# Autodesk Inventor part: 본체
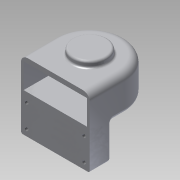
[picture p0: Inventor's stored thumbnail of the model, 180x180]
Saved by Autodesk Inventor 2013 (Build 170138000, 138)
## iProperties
Created: 2015-02
Part Number: 본체
Material: 알루미늄 6061
Document SubType Name: Modeling
Designer: Administrator
Density: 2.71 g/cm^3
Mass: 737.912 g
Surface Area: 727.955 cm^2
Volume: 272.292 cm^3
Author: Administrator
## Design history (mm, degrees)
sketch "스케치1"
  geometry: L1 (-50, -50)-(50, -50); L2 (50, 0)-(50, -50); L3 (-50, -50)-(-50, 0); A1 r 50 centre (0, 0) between (50, 0) and (-50, 0); 2 further points
  constraints: 6 end point, 2 midpoint, 2 point on circle, 2 tangent, 1 centre point, 1 coincident, 1 horizontal, 1 vertical alignment
  dimensions: "d1" = 100 distance of L1.start L1.end; "d2" = 50 distance from line of L1 A1.centre; "d3" = 50 radius of A1
extrude "돌출1" new body sketch "스케치1" stored distance "d4" = 50; taper "d5" = 0 deg
node "작업 평면1"
sketch "스케치2"
  geometry: C1 r 25 at (0, 0); 1 further point
  constraints: 1 centre point, 1 coincident
  dimensions: "d7" = 50 diameter of C1
extrude "돌출2" join sketch "스케치2" distance "d8" = 69; taper "d9" = 0 deg
feature "면 기울기1" dims angle "d10" = 20 deg
sketch "스케치3"
  geometry: L1 (-50, -50)-(50, -50) reference; L2 (50, -50)-(50, 0) reference; L3 (-50, 0)-(-50, -50) reference; L4 (-50, -50)-(50, -50); L5 (50, -50)-(50, -20); L6 (50, -20)-(34.641, -20); L7 (-50, -50)-(-50, -20); L8 (-34.641, -20)-(-50, -20); C1 r 21.36 at (0, 0) reference; C2 r 21.36 at (0, 0) reference; A1 r 40 centre (0, 0) between (-34.641, -20) and (34.641, -20); 2 further points
  constraints: 10 end point, 2 midpoint, 2 perpendicular, 2 point on circle, 2 point on line, 1 centre point, 1 coincident, 1 collinear, 1 horizontal alignment
  dimensions: "d11" = 30 distance of L1.end L5.end; "d12" = 80 diameter of A1
extrude "돌출3" join sketch "스케치3" distance "d13" = 49; taper "d14" = 0 deg
hole "구멍1" diameter "d17" = 20; stored, may be unused: countersink angle "d21" = 90 deg, drill point angle "d23" = 0 deg; dims "d18" = 6, "d19" = 28, "d20" = 10, "d22" = 30, "d24" = 10, "d25" = 10
sketch "스케치4"
  geometry: L1 (-34.641, -20)-(-50, -20) reference; L2 (-50, -20)-(-50, 0) reference; L3 (50, 0)-(50, -20) reference; L4 (50, -20)-(34.641, -20) reference; L5 (50, -50)-(-50, -50) reference; L6 (-50, -50)-(-50, -20) reference; L7 (-50, -20)-(-34.641, -20) reference; L8 (34.641, -20)-(50, -20) reference; L9 (50, -20)-(50, -50) reference; L10 (46, 0)-(46, -50); L11 (46, -50)-(-46, -50); L12 (-46, 0)-(-46, -50); C1 r 25 at (0, 0) reference; A1 r 50 centre (0, 0) between (50, 0) and (-50, 0) reference; A2 r 40 centre (0, 0) between (-34.641, -20) and (34.641, -20) reference; A3 r 40 centre (0, 0) between (-34.641, -20) and (34.641, -20) reference; A4 r 46 centre (0, 0) between (46, 0) and (-46, 0); 1 further point
  constraints: 6 end point, 2 perpendicular, 2 point on circle, 2 point on line, 2 tangent, 1 centre point, 1 coincident
  dimensions: "d27" = 4 radial gap between concentric circles of A4 A1
extrude "돌출4" cut sketch "스케치4" stored distance "d28" = 36; taper "d29" = 0 deg
sketch "스케치5"
  geometry: A1 r 46 centre (0, 0) between (46, 0) and (-46, 0) reference; 1 further point
  constraints: 1 coincident
hole "구멍2" sketch "스케치5" at (0, 0) diameter "d30" = 20; stored, may be unused: countersink angle "d34" = 90 deg, drill point angle "d36" = 0 deg; dims "d31" = 6, "d32" = 28, "d33" = 8, "d35" = 10
sketch "스케치6"
  geometry: L1 (100, -99)-(0, -99) reference; L2 (8.25, -57)-(91.75, -57); L3 (91.75, -57)-(91.75, -90); L4 (91.75, -90)-(8.25, -90); L5 (8.25, -90)-(8.25, -57); 7 further points
  constraints: 8 end point, 4 coincident, 2 midpoint, 2 parallel, 1 horizontal, 1 perpendicular, 1 vertical alignment
  dimensions: "d37" = 83.5 distance of L3.end L4.end; "d38" = 33 distance of L2.end L3.end; "d39" = 9 distance between parallel lines of L1 L4
hole "구멍3" sketch "스케치6" at (8.25, -57), (8.25, -90), (91.75, -90), (91.75, -57) diameter "d40" = 5.134; stored, may be unused: countersink angle "d44" = 90 deg, drill point angle "d46" = 118 deg; dims "d41" = 10, "d42" = 28, "d43" = 8, "d45" = 13
sketch "스케치7" dims "d47" = 36
  geometry: C1 r 14 at (0, 0) reference; C2 r 21.36 at (0, 0) reference; 2 further points
  constraints: 2 vertical alignment, 1 coincident, 2 other
hole "구멍4" sketch "스케치7" at (0, 18) diameter "d48" = 2.459; stored, may be unused: countersink angle "d52" = 90 deg, drill point angle "d54" = 118 deg; dims "d49" = 6, "d50" = 28, "d51" = 8, "d53" = 9
chamfer "모따기1" distance "d58" = 1; stored, may be unused: second distance "d59" = 2, angle "d60" = 45 deg
fillet "모깎기1" dims "d61" = 3, "d62" = 10, "d63" = 0.3, "d64" = 6
node "작업 평면2"
sketch "스케치8"
  geometry: L1 (40, 25)-(-40, 25) reference; L2 (-50, 15)-(50, 15) reference; L3 (-22, 34)-(22, 34) reference; A1 r 10 centre (40, 15) between (50, 15) and (40, 25) reference; A2 r 10 centre (-40, 15) between (-40, 25) and (-50, 15) reference; 3 further points
  constraints: 1 midpoint, 1 vertical alignment, 1 other
  dimensions: "d65" = 25 distance from line of point (0, 0) L1
feature "엠보싱1" sketch "스케치8" dims "d66" = 0.5, "d67" = 0
node "솔리드1"
pattern_circular "원형 패턴1" dims angle "d56" = 360 deg
node "투영된 루프1"
node "투영된 루프2"
node "투영된 루프3"
node "투영된 루프4"
other parameters: "d6" = 9
